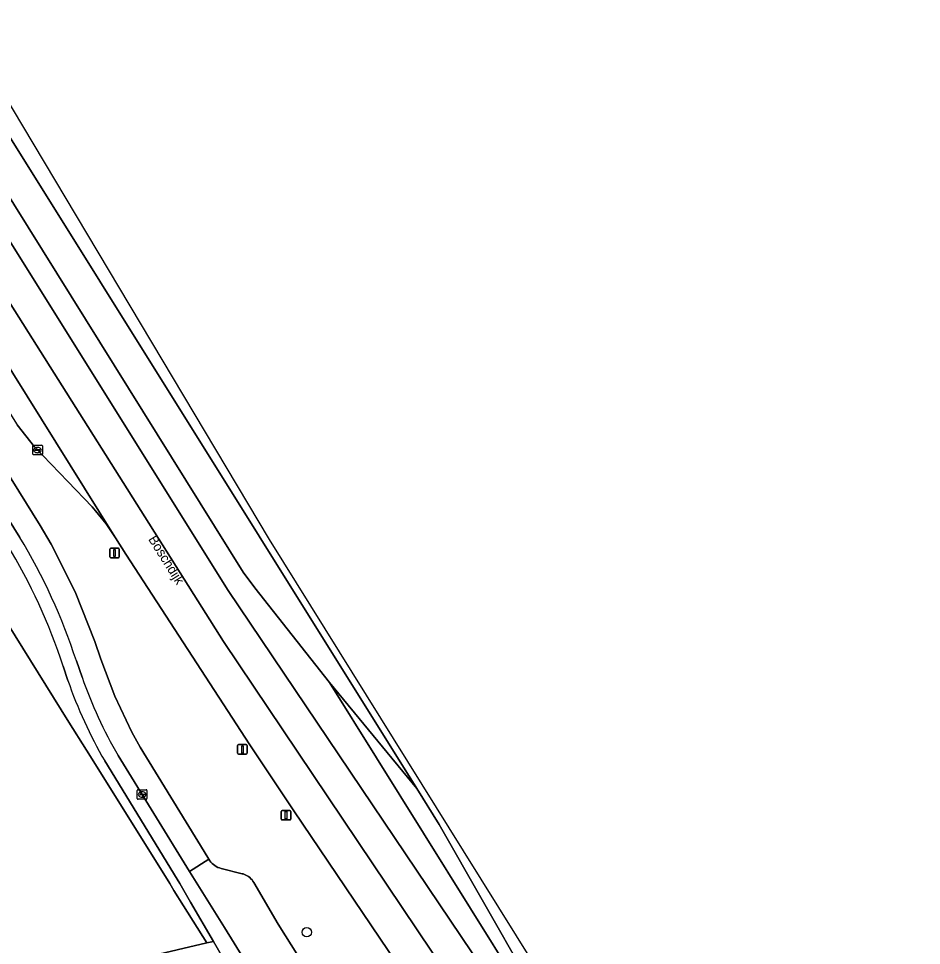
# Model space of a CAD drawing. Extents: x 158132 to 159664, y 385256 to 387218.
# Drawn here: x 159170.4 to 159264.8, y 386595.2 to 386692.1 of the extents above; entities that cross this region are included whole.
import ezdxf

# ---------------------------------------------------------------- set-up
doc = ezdxf.new("R2010")
doc.units = 0
for name, color, linetype in [('IMGEO_Berm_groen', 7, 'Continuous'), ('IMGEO_Berm_open', 7, 'Continuous'), ('IMGEO_Boom', 7, 'Continuous'), ('IMGEO_Fietspad_gesloten', 7, 'Continuous'), ('IMGEO_Groenvoorziening', 7, 'Continuous'), ('IMGEO_Hek', 7, 'Continuous'), ('IMGEO_Kolk', 7, 'Continuous'), ('IMGEO_Lichtmast', 7, 'Continuous'), ('IMGEO_Openbare_ruimte_label', 7, 'Continuous'), ('IMGEO_OVBaan_gesloten', 7, 'Continuous'), ('IMGEO_Rijbaan_lokaal_open', 7, 'Continuous'), ('IMGEO_Rijbaan_regionaal_gesloten', 7, 'Continuous'), ('IMGEO_Verkeersbordpaal', 7, 'Continuous'), ('IMGEO_Voetpad_open', 7, 'Continuous')]:
    doc.layers.add(name, color=color, linetype=linetype)

msp = doc.modelspace()

# ---------------------------------------------------------------- linework, layer by layer
at = {"layer": 'IMGEO_Berm_groen'}
for points in [[(159140.025, 386678.972), (159138.093, 386678.862), (159138.019, 386680.357), (159137.006, 386680.254), (159158.781, 386645.56), (159175.669, 386618.508), (159177.498, 386615.581), (159183.311, 386606.268), (159186.205, 386601.626), (159186.647, 386600.917), (159187.643, 386599.315), (159190.082, 386595.425), (159190.77, 386595.587), (159188.393, 386599.703), (159187.266, 386601.655), (159186.986, 386602.112), (159179.41, 386614.466)], [(159264.796, 386506.726), (159232.994, 386557.935), (159230.942, 386561.231), (159229.111, 386564.242), (159222.732, 386574.369), (159219.832, 386578.664), (159199.195, 386609.224), (159198.968, 386609.564), (159194.566, 386616.143), (159181.609, 386636.058), (159180.536, 386637.76), (159179.564, 386639.231), (159178.465, 386640.61), (159178.111, 386641.005), (159175.569, 386643.645), (159172.085, 386647.268), (159170.27, 386649.568)], [(159167.38, 386647.523), (159172.658, 386639.075), (159173.801, 386637.128), (159176.325, 386632.138), (159178.393, 386626.943), (159179.015, 386625.083), (159180.459, 386621.207), (159182.243, 386617.476), (159183.121, 386615.907), (159189.817, 386604.994), (159190.311, 386604.18), (159190.409, 386604.025), (159190.52, 386603.88), (159190.643, 386603.746), (159190.778, 386603.623), (159190.924, 386603.512), (159191.079, 386603.415), (159191.241, 386603.332), (159191.411, 386603.264), (159191.572, 386603.215), (159193.783, 386602.664), (159193.869, 386602.642), (159194.025, 386602.591), (159194.175, 386602.526), (159194.319, 386602.447), (159194.456, 386602.357), (159194.584, 386602.254), (159194.702, 386602.14), (159194.809, 386602.017), (159194.905, 386601.884), (159194.989, 386601.743), (159197.559, 386597.385), (159205.281, 386585.079)], [(159175.564, 386622.87), (159175.08, 386624.349)]]:
    msp.add_lwpolyline(points, dxfattribs=at)
for centre, radius, start, end in [((159118.241, 386605.831), 59.78, 18.04498, 31.47841), ((159221.045, 386638.602), 48.125, 199.08051, 210.10087)]:
    msp.add_arc(centre, radius, start, end, dxfattribs=at)
at = {"layer": 'IMGEO_Berm_open'}
for points in [[(159195.089, 386632.547), (159193.891, 386634.182), (159162.377, 386684.669)], [(159160.269, 386683.458), (159160.327, 386683.366), (159192.3, 386632.252), (159225.948, 386582.354), (159227.462, 386583.267), (159202.912, 386622.653), (159195.089, 386632.547)]]:
    msp.add_lwpolyline(points, dxfattribs=at)
at = {"layer": 'IMGEO_Boom'}
msp.add_circle((159200.53, 386596.55), 0.489, dxfattribs=at)
at = {"layer": 'IMGEO_Fietspad_gesloten'}
for points in [[(159138.243, 386689.799), (159141.938, 386683.988), (159142.038, 386683.935), (159146.111, 386677.137), (159146.114, 386677.064), (159170.533, 386637.824)], [(159180.821, 386615.009), (159188.272, 386602.912), (159190.311, 386604.18), (159189.817, 386604.994), (159183.121, 386615.907), (159182.243, 386617.476), (159180.459, 386621.207), (159179.015, 386625.083), (159178.393, 386626.943), (159176.325, 386632.138), (159173.801, 386637.128), (159172.658, 386639.075), (159167.38, 386647.523)], [(159176.446, 386624.924), (159177.042, 386623.196)]]:
    msp.add_lwpolyline(points, dxfattribs=at)
for centre, radius, start, end in [((159118.274, 386606.065), 61.152, 17.96253, 31.28827), ((159222.118, 386639.037), 47.779, 199.36269, 210.19203)]:
    msp.add_arc(centre, radius, start, end, dxfattribs=at)
at = {"layer": 'IMGEO_Groenvoorziening'}
msp.add_lwpolyline([(159168.154, 386591.073), (159175.178, 386591.91), (159190.082, 386595.425), (159187.643, 386599.315), (159186.647, 386600.917), (159186.205, 386601.626), (159183.311, 386606.268), (159177.498, 386615.581), (159175.669, 386618.508), (159158.781, 386645.56)], dxfattribs=at)
at = {"layer": 'IMGEO_Hek'}
for points in [[(159175.669, 386618.508), (159158.781, 386645.56)], [(159186.205, 386601.626), (159183.311, 386606.268), (159177.498, 386615.581), (159175.669, 386618.508)], [(159190.082, 386595.425), (159187.643, 386599.315), (159186.647, 386600.917), (159186.205, 386601.626)]]:
    msp.add_lwpolyline(points, dxfattribs=at)
at = {"layer": 'IMGEO_Kolk'}
for p, q in [((159171.892, 386646.522), (159171.892, 386647.374)), ((159171.967, 386647.448), (159172.819, 386647.448)), ((159172.151, 386646.942), (159172.151, 386646.954)), ((159172.589, 386646.905), (159172.191, 386646.905)), ((159172.194, 386646.991), (159172.592, 386646.991)), ((159172.38, 386647.228), (159172.405, 386647.228)), ((159172.635, 386646.954), (159172.635, 386646.942)), ((159172.893, 386647.374), (159172.893, 386646.522)), ((159172.819, 386646.448), (159171.967, 386646.448)), ((159172.403, 386646.668), (159172.378, 386646.668)), ((159182.82, 386610.522), (159182.82, 386611.374)), ((159182.895, 386611.448), (159183.747, 386611.448)), ((159183.079, 386610.942), (159183.079, 386610.954)), ((159183.517, 386610.905), (159183.119, 386610.905)), ((159183.122, 386610.991), (159183.52, 386610.991)), ((159183.308, 386611.228), (159183.333, 386611.228)), ((159183.563, 386610.954), (159183.563, 386610.942)), ((159183.821, 386611.374), (159183.821, 386610.522)), ((159183.747, 386610.448), (159182.895, 386610.448)), ((159183.331, 386610.668), (159183.306, 386610.668))]:
    msp.add_line(p, q, dxfattribs=at)
for points in [[(159171.892, 386646.522), (159171.892, 386647.374)], [(159171.967, 386647.448), (159172.819, 386647.448)], [(159172.893, 386647.374), (159172.893, 386646.522)], [(159172.819, 386646.448), (159171.967, 386646.448)], [(159182.82, 386610.522), (159182.82, 386611.374)], [(159182.895, 386611.448), (159183.747, 386611.448)], [(159183.821, 386611.374), (159183.821, 386610.522)], [(159183.747, 386610.448), (159182.895, 386610.448)]]:
    msp.add_lwpolyline(points, dxfattribs=at)
for centre, radius, start, end in [((159171.969, 386647.372), 0.0765, 91.55205, 178.44795), ((159171.969, 386647.372), 0.0765, 91.55205, 178.44795), ((159172.191, 386646.951), 0.0403, 85.87752, 175.75265), ((159172.188, 386646.941), 0.0366, 178.93798, 274.71019), ((159172.592, 386646.948), 0.043, 264.86636, 352.45326), ((159172.596, 386646.953), 0.0386, 1.73085, 96.63898), ((159172.817, 386647.372), 0.0765, 1.55205, 88.44795), ((159172.817, 386647.372), 0.0765, 1.55205, 88.44795), ((159171.969, 386646.524), 0.0765, 181.55205, 268.44795), ((159171.969, 386646.524), 0.0765, 181.55205, 268.44795), ((159172.817, 386646.524), 0.0765, 271.55205, 358.44795), ((159172.817, 386646.524), 0.0765, 271.55205, 358.44795), ((159182.897, 386611.372), 0.0765, 91.55205, 178.44795), ((159182.897, 386611.372), 0.0765, 91.55205, 178.44795), ((159183.119, 386610.951), 0.0403, 85.87752, 175.75265), ((159183.116, 386610.941), 0.0366, 178.93798, 274.71019), ((159183.52, 386610.948), 0.043, 264.86636, 352.45326), ((159183.524, 386610.953), 0.0386, 1.73085, 96.63898), ((159183.745, 386611.372), 0.0765, 1.55205, 88.44795), ((159183.745, 386611.372), 0.0765, 1.55205, 88.44795), ((159182.897, 386610.524), 0.0765, 181.55205, 268.44795), ((159182.897, 386610.524), 0.0765, 181.55205, 268.44795), ((159183.745, 386610.524), 0.0765, 271.55205, 358.44795), ((159183.745, 386610.524), 0.0765, 271.55205, 358.44795)]:
    msp.add_arc(centre, radius, start, end, dxfattribs=at)
for centre, major_axis, ratio, start_param, end_param in [((159172.379, 386646.948), (-0.387, 0.002), 0.722429, 4.712389, 7.853982), ((159172.404, 386646.948), (-0.39, 0.002), 0.717154, 1.570796, 4.712389), ((159183.307, 386610.948), (-0.387, 0.002), 0.722429, 4.712389, 7.853982), ((159183.332, 386610.948), (-0.39, 0.002), 0.717154, 1.570796, 4.712389)]:
    msp.add_ellipse(centre, major_axis=major_axis, ratio=ratio, start_param=start_param, end_param=end_param, dxfattribs=at)
at = {"layer": 'IMGEO_Lichtmast'}
for p, q in [((159179.948, 386635.792), (159179.948, 386636.592)), ((159179.948, 386636.592), (159179.948, 386635.792)), ((159180.048, 386636.692), (159180.838, 386636.692)), ((159180.838, 386636.692), (159180.048, 386636.692)), ((159180.938, 386636.592), (159180.938, 386635.792)), ((159180.938, 386635.792), (159180.938, 386636.592)), ((159180.838, 386635.692), (159180.048, 386635.692)), ((159180.048, 386635.692), (159180.838, 386635.692)), ((159193.309, 386615.255), (159193.309, 386616.055)), ((159193.309, 386616.055), (159193.309, 386615.255)), ((159193.409, 386616.155), (159194.199, 386616.155)), ((159194.199, 386616.155), (159193.409, 386616.155)), ((159194.299, 386616.055), (159194.299, 386615.255)), ((159194.299, 386615.255), (159194.299, 386616.055)), ((159194.199, 386615.155), (159193.409, 386615.155)), ((159193.409, 386615.155), (159194.199, 386615.155))]:
    msp.add_line(p, q, dxfattribs=at)
for points in [[(159180.368, 386636.567), (159180.518, 386636.567), (159180.518, 386635.817), (159180.368, 386635.817), (159180.368, 386636.567)], [(159193.729, 386616.03), (159193.879, 386616.03), (159193.879, 386615.28), (159193.729, 386615.28), (159193.729, 386616.03)]]:
    msp.add_lwpolyline(points, dxfattribs=at)
for centre, start, end in [((159180.048, 386636.592), 90, 180), ((159180.048, 386636.592), 90, 180), ((159180.838, 386636.592), 0, 90), ((159180.838, 386636.592), 360, 90), ((159180.048, 386635.792), 180, 270), ((159180.048, 386635.792), 180, 270), ((159180.838, 386635.792), 270, 0), ((159180.838, 386635.792), 270, 0), ((159193.409, 386616.055), 90, 180), ((159193.409, 386616.055), 90, 180), ((159194.199, 386616.055), 0, 90), ((159194.199, 386616.055), 360, 90), ((159193.409, 386615.255), 180, 270), ((159193.409, 386615.255), 180, 270), ((159194.199, 386615.255), 270, 0), ((159194.199, 386615.255), 270, 0)]:
    msp.add_arc(centre, 0.1, start, end, dxfattribs=at)
at = {"layer": 'IMGEO_OVBaan_gesloten'}
msp.add_lwpolyline([(159151.361, 386683.988), (159151.976, 386681.947), (159152.989, 386678.663), (159153.22, 386677.762), (159153.755, 386676.032), (159157.015, 386670.747), (159161.293, 386663.809), (159170.27, 386649.568), (159172.085, 386647.268), (159175.569, 386643.645), (159178.111, 386641.005), (159178.465, 386640.61), (159179.564, 386639.231), (159180.536, 386637.76), (159180.301, 386638.143), (159150.478, 386685.963)], dxfattribs=at)
at = {"layer": 'IMGEO_Rijbaan_lokaal_open'}
for points in [[(159205.281, 386585.079), (159197.559, 386597.385), (159194.989, 386601.743), (159194.905, 386601.884), (159194.809, 386602.017), (159194.702, 386602.14), (159194.584, 386602.254), (159194.456, 386602.357), (159194.319, 386602.447), (159194.175, 386602.526), (159194.025, 386602.591), (159193.869, 386602.642), (159193.783, 386602.664), (159191.572, 386603.215), (159191.411, 386603.264), (159191.241, 386603.332), (159191.079, 386603.415), (159190.924, 386603.512), (159190.778, 386603.623), (159190.643, 386603.746), (159190.52, 386603.88), (159190.409, 386604.025), (159190.311, 386604.18), (159188.272, 386602.912), (159189.827, 386600.388), (159191.925, 386597.033), (159196.242, 386590.04)], [(159167.303, 386586.153), (159176.641, 386587.244), (159192.213, 386592.027), (159192.734, 386592.187), (159190.77, 386595.587), (159190.082, 386595.425), (159175.178, 386591.91), (159168.154, 386591.073)]]:
    msp.add_lwpolyline(points, dxfattribs=at)
at = {"layer": 'IMGEO_Rijbaan_regionaal_gesloten'}
for points in [[(159229.657, 386584.591), (159216.91, 386605.043), (159196.624, 386637.589), (159164.114, 386692.051), (159162.374, 386690.992), (159212.025, 386611.559), (159214.361, 386607.797), (159228.151, 386583.682), (159229.657, 386584.591)], [(159162.374, 386690.992), (159159.505, 386689.244), (159160.596, 386687.509), (159162.377, 386684.669), (159193.891, 386634.182), (159195.089, 386632.547), (159202.912, 386622.653), (159212.025, 386611.559)], [(159160.327, 386683.366), (159160.269, 386683.458), (159158.561, 386686.172), (159157.444, 386687.955), (159154.015, 386686.975), (159157.237, 386681.723), (159191.817, 386626.926), (159222.985, 386580.566), (159225.948, 386582.354), (159192.3, 386632.252)], [(159154.015, 386686.975), (159150.478, 386685.963), (159180.301, 386638.143), (159180.536, 386637.76), (159181.609, 386636.058), (159194.566, 386616.143), (159198.968, 386609.564), (159199.195, 386609.224), (159219.832, 386578.664), (159222.985, 386580.566), (159191.817, 386626.926), (159157.237, 386681.723)], [(159212.025, 386611.559), (159202.912, 386622.653), (159227.462, 386583.267), (159228.151, 386583.682), (159214.361, 386607.797)]]:
    msp.add_lwpolyline(points, close=True, dxfattribs=at)
at = {"layer": 'IMGEO_Verkeersbordpaal'}
for p, q in [((159197.869, 386608.381), (159197.869, 386609.181)), ((159197.869, 386609.181), (159197.869, 386608.381)), ((159197.969, 386609.281), (159198.759, 386609.281)), ((159198.759, 386609.281), (159197.969, 386609.281)), ((159198.859, 386609.181), (159198.859, 386608.381)), ((159198.859, 386608.381), (159198.859, 386609.181)), ((159198.759, 386608.281), (159197.969, 386608.281)), ((159197.969, 386608.281), (159198.759, 386608.281))]:
    msp.add_line(p, q, dxfattribs=at)
msp.add_lwpolyline([(159198.289, 386609.156), (159198.439, 386609.156), (159198.439, 386608.406), (159198.289, 386608.406), (159198.289, 386609.156)], dxfattribs=at)
for centre, start, end in [((159197.969, 386609.181), 90, 180), ((159197.969, 386609.181), 90, 180), ((159198.759, 386609.181), 0, 90), ((159198.759, 386609.181), 360, 90), ((159197.969, 386608.381), 180, 270), ((159197.969, 386608.381), 180, 270), ((159198.759, 386608.381), 270, 0), ((159198.759, 386608.381), 270, 0)]:
    msp.add_arc(centre, 0.1, start, end, dxfattribs=at)
at = {"layer": 'IMGEO_Voetpad_open'}
for points in [[(159170.533, 386637.824), (159146.114, 386677.064)], [(159177.042, 386623.196), (159176.446, 386624.924)], [(159175.08, 386624.349), (159175.564, 386622.87)], [(159197.665, 386587.771), (159196.242, 386590.04), (159191.925, 386597.033), (159189.827, 386600.388), (159188.272, 386602.912), (159180.821, 386615.009)], [(159179.41, 386614.466), (159186.986, 386602.112), (159187.266, 386601.655), (159188.393, 386599.703), (159190.77, 386595.587), (159192.734, 386592.187), (159194.116, 386589.793), (159250.168, 386500), (159253.146, 386495.229), (159254.996, 386496.361), (159253.773, 386498.341), (159252.73, 386500), (159231.678, 386533.486), (159209.625, 386568.892), (159197.665, 386587.771)]]:
    msp.add_lwpolyline(points, dxfattribs=at)
for centre, radius, start, end in [((159118.274, 386606.065), 61.152, 17.96253, 31.28827), ((159118.241, 386605.831), 59.78, 18.04498, 31.47841), ((159221.045, 386638.602), 48.125, 199.08051, 210.10087), ((159222.118, 386639.037), 47.779, 199.36269, 210.19203)]:
    msp.add_arc(centre, radius, start, end, dxfattribs=at)

# ---------------------------------------------------------------- texts
at = {"layer": 'IMGEO_Openbare_ruimte_label'}
msp.add_text('Boschdijk', height=1, rotation=302.00538, dxfattribs=at).set_placement((159183.926, 386637.632))

doc.saveas('drawing.dxf')
